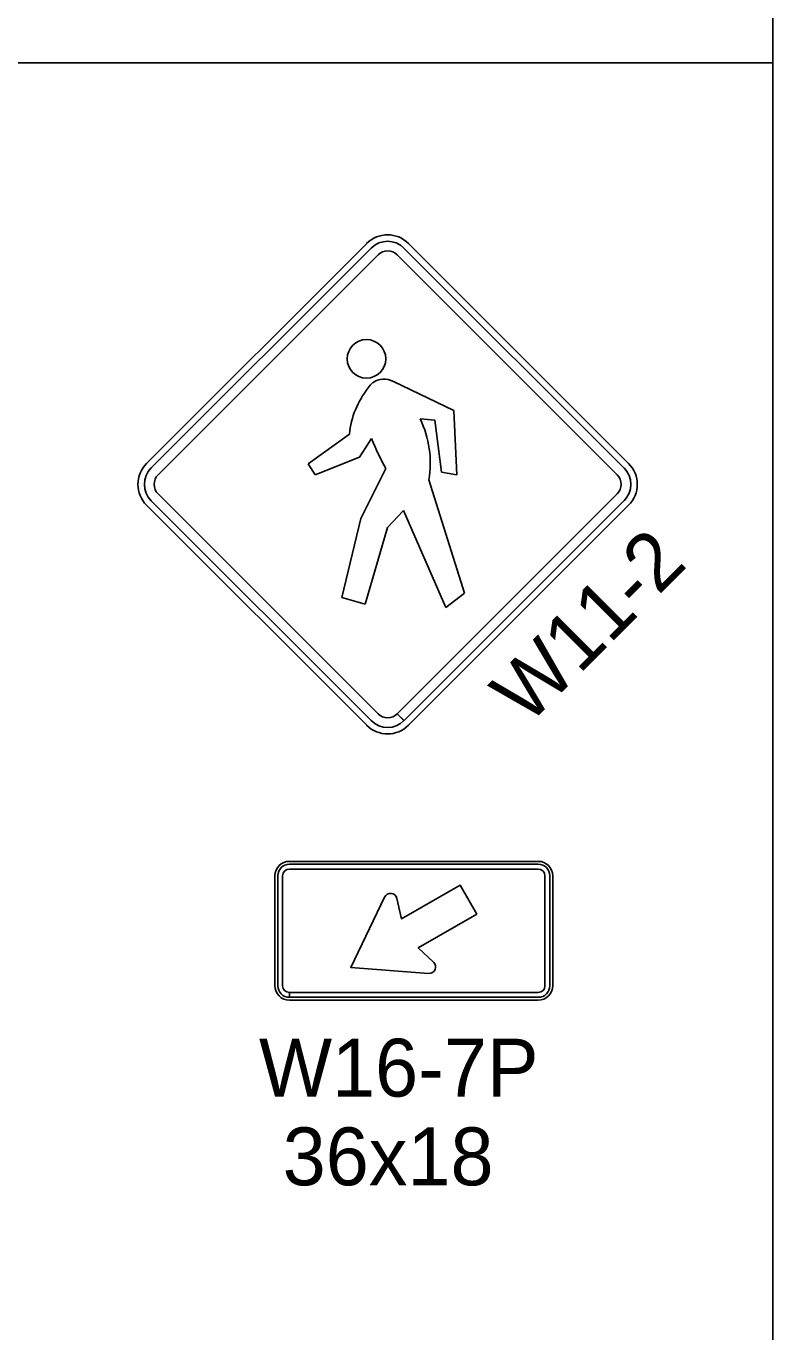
# Model space of a CAD drawing. Extents: x 1458 to 4498, y 17709 to 24109.
# Drawn here: x 2939.3 to 3132.7, y 21127.9 to 21466.4 of the extents above; entities that cross this region are included whole.
import ezdxf

# ---------------------------------------------------------------- set-up
doc = ezdxf.new("R2010")
doc.units = 0
for name, color, linetype in [('P_ODOT_PLAN_TBlock', 7, 'Continuous'), ('P_TRAF_SIGN_SignDetails', 7, 'Continuous'), ('P_TRAF_TCP_General', 7, 'Continuous')]:
    doc.layers.add(name, color=color, linetype=linetype)

msp = doc.modelspace()

# ---------------------------------------------------------------- linework, layer by layer
at = {"layer": 'P_ODOT_PLAN_TBlock'}
for p, q in [((3132.73, 21909.14), (3132.73, 20667.08)), ((2488.57, 21456.82), (3132.73, 21456.82))]:
    msp.add_line(p, q, dxfattribs=at)
at = {"layer": 'P_TRAF_SIGN_SignDetails'}
for p, q in [((3034.43, 21374.21), (3034.43, 21374.22)), ((3034.43, 21374.22), (3050.08, 21366.76)), ((3034.43, 21374.21), (3034.43, 21374.22)), ((3034.43, 21374.21), (3034.43, 21374.22)), ((3034.43, 21374.22), (3050.08, 21366.76)), ((3034.43, 21374.21), (3034.43, 21374.22)), ((3050.08, 21366.76), (3050.87, 21350.02)), ((3050.08, 21366.76), (3050.87, 21350.02)), ((3045.12, 21364.26), (3041.34, 21364.54)), ((3045.12, 21364.26), (3041.34, 21364.54)), ((3046.87, 21350.72), (3045.12, 21364.26)), ((3046.87, 21350.72), (3045.12, 21364.26)), ((3012.3, 21352.91), (3023.01, 21360.62)), ((3012.3, 21352.91), (3023.01, 21360.62)), ((3028.77, 21359.45), (3025.62, 21354.64)), ((3028.77, 21359.45), (3025.62, 21354.64)), ((3014.18, 21350.07), (3012.3, 21352.91)), ((3014.18, 21350.07), (3012.3, 21352.91)), ((3025.62, 21354.64), (3014.18, 21350.07)), ((3025.62, 21354.64), (3014.18, 21350.07)), ((3025.99, 21338.73), (3032.44, 21351.66)), ((3025.99, 21338.73), (3032.44, 21351.66)), ((3043.57, 21348.77), (3052.81, 21319.35)), ((3043.57, 21348.77), (3052.81, 21319.35)), ((3050.87, 21350.02), (3046.87, 21350.72)), ((3050.87, 21350.02), (3046.87, 21350.72)), ((3021.08, 21318.3), (3025.99, 21338.73)), ((3021.08, 21318.3), (3025.99, 21338.73)), ((3037.05, 21340.82), (3032.89, 21336.41)), ((3037.05, 21340.82), (3032.89, 21336.41)), ((3047.97, 21315.65), (3037.05, 21340.82)), ((3047.97, 21315.65), (3037.05, 21340.82)), ((3032.89, 21336.41), (3027.13, 21316.54)), ((3032.89, 21336.41), (3027.13, 21316.54)), ((3027.13, 21316.54), (3021.08, 21318.3)), ((3027.13, 21316.54), (3021.08, 21318.3)), ((3052.81, 21319.35), (3047.97, 21315.65)), ((3052.81, 21319.35), (3047.97, 21315.65))]:
    msp.add_line(p, q, dxfattribs=at)
for points in [[(3056.03, 21236.2), (3051.67, 21243.74), (3036.51, 21234.98), (3035.3, 21240.27)], [(3032.12, 21240.62), (3023.38, 21222.37), (3043.55, 21220.82)], [(3044.84, 21223.75), (3040.87, 21227.45), (3056.03, 21236.2)]]:
    msp.add_lwpolyline(points, dxfattribs=at)
msp.add_circle((3027.44, 21380.11), 4.99, dxfattribs=at)
msp.add_circle((3027.44, 21380.11), 4.99, dxfattribs=at)
for centre, radius, start, end in [((3045.85, 21358.27), 22.97, 141.4976, 174.1516), ((3045.85, 21358.27), 22.97, 141.4976, 174.1516), ((3034.64, 21367.92), 8.21, 133.0399, 145.5045), ((3034.64, 21367.92), 8.21, 133.0399, 145.5045), ((3031.97, 21369.82), 5.04, 60.6785, 125.4757), ((3031.97, 21369.82), 5.04, 60.6785, 125.4757), ((3018.22, 21353.23), 25.74, 349.9861, 26.0599), ((3018.22, 21353.23), 25.74, 349.9861, 26.0599), ((3094.84, 21385.85), 71.16, 201.7818, 208.7113), ((3094.84, 21385.85), 71.16, 201.7818, 208.7113), ((3033.65, 21239.89), 1.69, 12.9427, 154.3997), ((3043.68, 21222.51), 1.69, 265.6003, 47.0573)]:
    msp.add_arc(centre, radius, start, end, dxfattribs=at)
at = {"layer": 'P_TRAF_TCP_General'}
for p, q in [((3027.49, 21410.01), (2970.48, 21353.01)), ((3095.34, 21353.01), (3038.34, 21410.01)), ((3028.67, 21408.83), (2971.66, 21351.83)), ((2973.43, 21350.06), (3030.44, 21407.06)), ((3035.38, 21407.06), (3092.39, 21350.06)), ((3035.38, 21407.06), (3092.39, 21350.06)), ((3094.16, 21351.83), (3037.15, 21408.83)), ((2970.48, 21342.16), (3027.49, 21285.15)), ((2971.66, 21343.34), (3028.67, 21286.34)), ((3030.44, 21288.1), (2973.43, 21345.11)), ((3092.39, 21345.11), (3035.4, 21288.12)), ((3037.17, 21286.36), (3094.16, 21343.34)), ((3038.34, 21285.15), (3095.34, 21342.16)), ((3037.15, 21286.34), (3035.38, 21288.1)), ((3037.15, 21286.34), (3035.38, 21288.1)), ((3035.4, 21288.12), (3037.17, 21286.36)), ((3035.4, 21288.12), (3037.17, 21286.36)), ((3071.94, 21249.87), (3007.47, 21249.87)), ((3071.94, 21249.12), (3007.47, 21249.12)), ((3007.47, 21247.87), (3071.94, 21247.87)), ((3003.72, 21246.12), (3003.72, 21217.63)), ((3004.47, 21246.12), (3004.47, 21217.63)), ((3005.72, 21217.63), (3005.72, 21246.12)), ((3073.69, 21246.12), (3073.69, 21217.63)), ((3074.94, 21217.63), (3074.94, 21246.12)), ((3075.69, 21217.63), (3075.69, 21246.12)), ((3007.47, 21214.64), (3007.47, 21215.89)), ((3007.47, 21213.89), (3071.94, 21213.89)), ((3071.94, 21215.89), (3007.48, 21215.89)), ((3007.48, 21215.89), (3007.48, 21214.64)), ((3007.48, 21214.64), (3071.94, 21214.64))]:
    msp.add_line(p, q, dxfattribs=at)
for centre, radius, start, end in [((3032.91, 21404.59), 7.67, 45, 135), ((3032.91, 21404.59), 6, 45, 135), ((3032.91, 21404.59), 3.5, 45, 135), ((2975.91, 21347.58), 7.67, 135, 225), ((3089.92, 21347.58), 7.67, 315, 45), ((2975.91, 21347.58), 6, 135, 225), ((2975.91, 21347.58), 6, 135, 225), ((2975.91, 21347.58), 3.5, 135, 225), ((3089.92, 21347.58), 3.5, 315, 45), ((3089.92, 21347.58), 6, 315, 45), ((3032.91, 21290.58), 3.5, 225, 315), ((3032.91, 21290.58), 7.67, 225, 315), ((3032.91, 21290.58), 6, 225, 315), ((3007.47, 21246.12), 3.75, 90, 180), ((3007.47, 21246.12), 3, 90, 180), ((3007.47, 21246.12), 1.75, 90, 180), ((3071.94, 21246.12), 3.75, 0, 90), ((3071.94, 21246.12), 3, 0, 90), ((3071.94, 21246.12), 1.75, 0, 90), ((3007.47, 21217.63), 3.75, 180, 270), ((3007.47, 21217.63), 3, 180, 270), ((3007.47, 21217.63), 1.75, 180, 270), ((3071.94, 21217.63), 3, 270, 0), ((3071.94, 21217.63), 1.75, 270, 0), ((3071.94, 21217.63), 3.75, 270, 0)]:
    msp.add_arc(centre, radius, start, end, dxfattribs=at)

# ---------------------------------------------------------------- texts
msp.add_text('W11-2', height=14.994, rotation=45, dxfattribs=at).set_placement((3069.17, 21284.79))
for s, p in [('W16-7P', (2999.59, 21188.9)), ('36x18', (3005.73, 21165.91))]:
    msp.add_text(s, height=14.994, dxfattribs=at).set_placement(p)

doc.saveas('drawing.dxf')
